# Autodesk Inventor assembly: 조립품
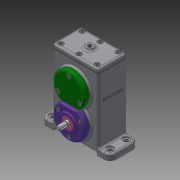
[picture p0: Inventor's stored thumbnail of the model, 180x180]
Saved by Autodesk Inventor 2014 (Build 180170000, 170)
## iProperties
Created: 2020-05
Part Number: 조립품
Document SubType Name: Assembly
Designer: kh
Author: kh
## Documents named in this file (24)
- C:\Users\kh\Desktop\600506V1032\조립품.iam
- C:\Users\kh\Desktop\600506V1032\본체.ipt
- C:\Users\kh\Desktop\600506V1032\개스킷 A.ipt
- C:\Users\kh\Desktop\600506V1032\개스킷 B.ipt
- C:\Users\kh\Desktop\600506V1032\개스킷 C.ipt
- C:\Users\kh\Desktop\600506V1032\베어링 6001.ipt
- 베어링 6001.ipt
- C:\Users\kh\Desktop\600506V1032\베어링 6002.ipt
- 베어링 6002.ipt
- C:\Users\kh\Desktop\600506V1032\볼트 M4.ipt
- C:\Users\kh\Desktop\600506V1032\스퍼기어 A.ipt
- C:\Users\kh\Desktop\600506V1032\스퍼기어 B.ipt
- C:\Users\kh\Desktop\600506V1032\오일 실 10 20 7.ipt
- C:\Users\kh\Desktop\600506V1032\오일 실 12 22 7.ipt
- C:\Users\kh\Desktop\600506V1032\축 A.ipt
- C:\Users\kh\Desktop\600506V1032\축 B.ipt
- C:\Users\kh\Desktop\600506V1032\칼라.ipt
- C:\Users\kh\Desktop\600506V1032\커버 A.ipt
- C:\Users\kh\Desktop\600506V1032\커버 B.ipt
- C:\Users\kh\Desktop\600506V1032\커버 C.ipt
- C:\Users\kh\Desktop\600506V1032\커버 D.ipt
- C:\Users\kh\Desktop\600506V1032\커버 E.ipt
- C:\Users\kh\Desktop\600506V1032\키 4 x 4 x 12.ipt
- C:\Users\kh\Desktop\600506V1032\키 5 x 5 x 12.ipt
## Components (5 placed, 3 different names)
1. 개스킷 A:1
2. 개스킷 B:1
3. 개스킷 C:1
4. 개스킷 B:2
5. 개스킷 B:3
